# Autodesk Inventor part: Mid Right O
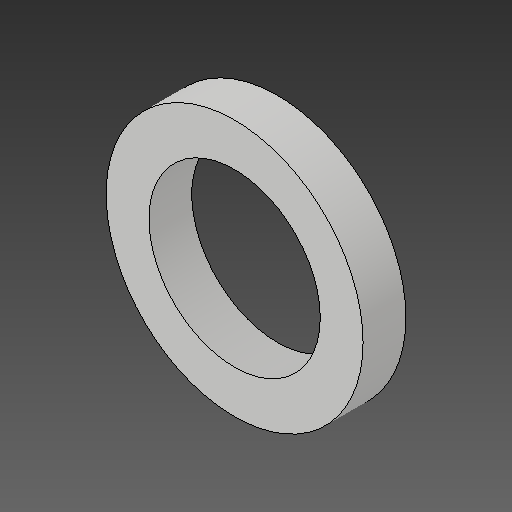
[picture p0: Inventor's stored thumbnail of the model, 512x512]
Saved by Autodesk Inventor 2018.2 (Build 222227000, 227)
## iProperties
Created: 2018-03
Part Number: Mid Right O
Material: Generic
Document SubType Name: Modeling
Designer: PeterMaxwell-Stewart
Mass: 1.9635 g
Surface Area: 15.708 cm^2
Volume: 1.9635 cm^3
Density: 1 g/cm^3
Appearance: Default
Author: PeterMaxwell-Stewart
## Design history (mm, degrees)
derived "O's and X's.ipt"
feature "Mid Right O::O's and X's.ipt" dims "d0" = 10
tag "TaggingFeature1"
body "Solid1"
